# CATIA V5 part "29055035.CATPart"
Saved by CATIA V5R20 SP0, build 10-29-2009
Part number: 29055035
Definition: NONE
Nomenclature: 29055035
Source: Unknown
Description: 29055035
Bounding box of the stored display mesh (mm): x -17.5 to 44.548, y -41.5 to 76.048, z -31.5 to 31.5
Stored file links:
  C:\Users\Utente\Desktop\IO LAVORO\3D X SITO CF\X SITO\PLASTICA\RF1\29055035.CATPart
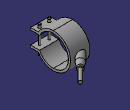
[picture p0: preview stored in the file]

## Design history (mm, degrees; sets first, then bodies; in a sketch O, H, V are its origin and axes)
Body1 "29055035" (main body)
  Solid1: solid without history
